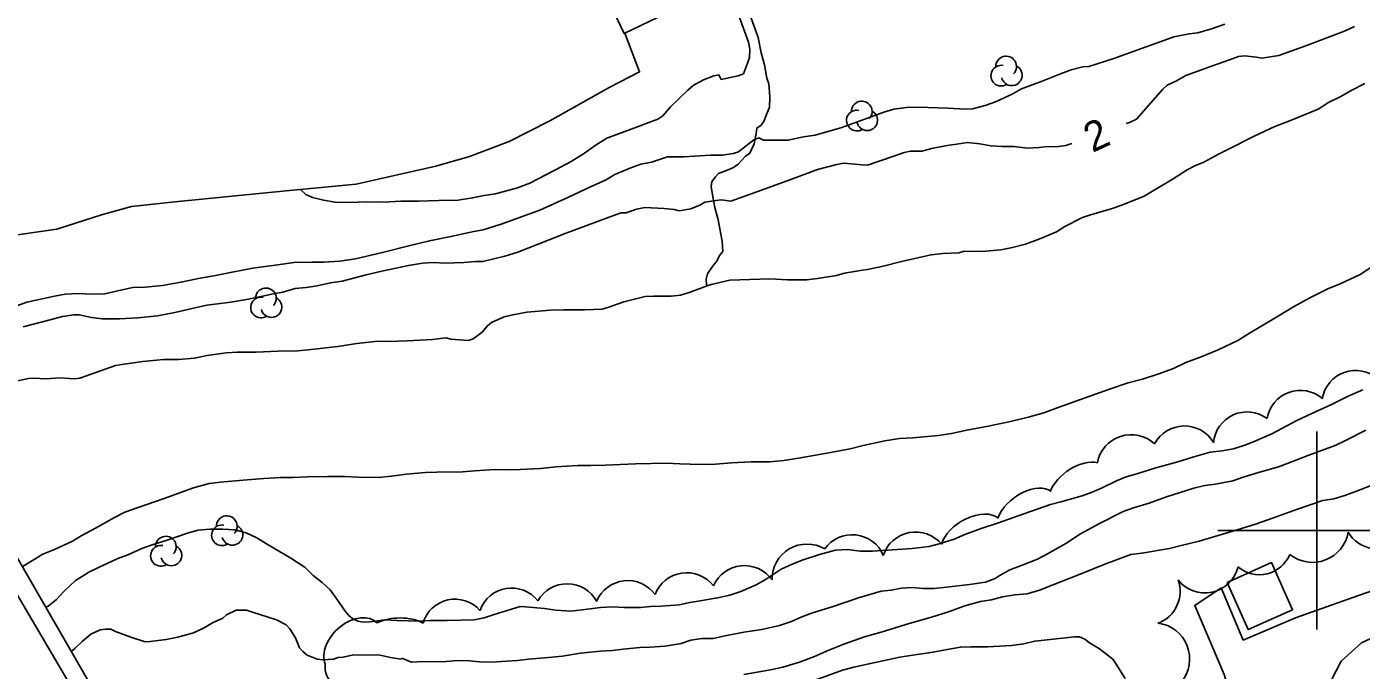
# Model space of a CAD drawing. Extents: x 381879 to 384696, y 5564785 to 5567594.
# Drawn here: x 383869.7 to 384004.5, y 5566385.9 to 5566450.9 of the extents above; entities that cross this region are included whole.
import ezdxf

# ---------------------------------------------------------------- set-up
doc = ezdxf.new("R2010")
doc.units = 0
for name, color, linetype in [('Niveau 19', 7, 'Continuous'), ('Niveau 2', 7, 'Continuous'), ('Niveau 21', 7, 'Continuous'), ('Niveau 26', 7, 'Continuous'), ('Niveau 31', 7, 'Continuous'), ('Niveau 4', 7, 'Continuous'), ('Niveau 44', 7, 'Continuous'), ('Niveau 52', 7, 'Continuous'), ('Niveau 61', 7, 'Continuous')]:
    doc.layers.add(name, color=color, linetype=linetype)

msp = doc.modelspace()

# ---------------------------------------------------------------- linework, layer by layer
at = {"layer": 'Niveau 19'}
msp.add_lwpolyline([(384009.04, 5566371.75), (384005.19, 5566373.71), (384000.87, 5566375.14), (383999.42, 5566377.48), (384000.4, 5566382.81), (384002.46, 5566386.78), (384004.5, 5566388.63), (384007.19, 5566389.9), (384009.07, 5566391.03), (384009.06, 5566392.88), (384007.91, 5566394.71), (384004.22, 5566393.43), (383997.83, 5566391.16), (383992.57, 5566388.92), (383990.33, 5566394.2), (383987.67, 5566392.42), (383990.65, 5566385.45), (383993.25, 5566376.84), (383995.32, 5566369.47), (383995.77, 5566367.6)], dxfattribs=at)
at = {"layer": 'Niveau 2'}
for points in [[(383941.69, 5566451.86), (383942.58, 5566449.36), (383942.72, 5566448.64), (383942.68, 5566447.82), (383942.49, 5566447.22), (383942.08, 5566446.17), (383941.54, 5566445.96), (383939.83, 5566445.59), (383939.6, 5566446.04), (383939.1, 5566445.94), (383938.05, 5566445.56), (383937, 5566444.99), (383936.46, 5566444.49), (383934.73, 5566442.82), (383933.95, 5566441.92), (383933.43, 5566441.58), (383932.8, 5566441.33), (383930.73, 5566440.57), (383928.29, 5566439.64), (383927.2, 5566438.99), (383925.94, 5566438.08), (383924.69, 5566437.31), (383923.03, 5566436.41), (383920.51, 5566435.09), (383919.27, 5566434.64), (383917.04, 5566434.04), (383915.89, 5566433.87), (383914.73, 5566433.62), (383913.08, 5566433.36), (383912.34, 5566433.4)], [(383990.7, 5566451.19), (383989.35, 5566450.69), (383987.98, 5566450.3), (383987.12, 5566450.2), (383985.55, 5566449.91), (383984.91, 5566449.67), (383982.28, 5566448.72), (383979.5, 5566447.7), (383976.97, 5566446.91), (383976.36, 5566446.86), (383975.17, 5566446.55), (383974.1, 5566446.16), (383972.26, 5566445.43), (383970.18, 5566444.65), (383969.21, 5566444.11), (383967.55, 5566443.33)], [(384003.82, 5566450.93), (384002.85, 5566450.51), (384001.27, 5566449.88), (383998.8, 5566448.95), (383996.16, 5566448), (383994.45, 5566447.73), (383993.92, 5566447.84), (383992.7, 5566447.99), (383992.1, 5566447.92), (383991.56, 5566447.72), (383989.45, 5566446.98), (383986.77, 5566445.98)], [(383986.77, 5566445.98), (383985.83, 5566445.45), (383984.89, 5566445), (383984.44, 5566444.6), (383983.72, 5566443.76), (383981.78, 5566441.57), (383981.08, 5566441.25), (383980.75, 5566441.13)], [(383967.55, 5566443.33), (383966.5, 5566442.95), (383965.22, 5566442.61), (383964.48, 5566442.6), (383962.74, 5566442.69), (383959.72, 5566442.8), (383958.54, 5566442.76), (383957.26, 5566442.59), (383956.27, 5566442.27), (383954.6, 5566441.66), (383952.03, 5566440.73), (383949.33, 5566439.96), (383948.15, 5566439.8), (383946.61, 5566439.46), (383944.1, 5566439.46), (383943.64, 5566439.67), (383943.13, 5566439.49), (383942.36, 5566438.87), (383941.57, 5566438.28), (383941.08, 5566438.11), (383939.97, 5566437.95), (383938.76, 5566437.94), (383936.05, 5566437.78), (383934.42, 5566437.75), (383933.92, 5566437.61), (383932.79, 5566437.21), (383931.71, 5566437.01), (383930.71, 5566436.67), (383929.08, 5566435.99), (383928.15, 5566435.4), (383926.7, 5566434.76), (383924.36, 5566433.66), (383921.52, 5566432.37), (383920.3, 5566431.93), (383917.62, 5566430.95), (383915.78, 5566430.37), (383914.84, 5566430.21), (383912.53, 5566429.71), (383910.37, 5566429.29), (383908.28, 5566428.76), (383905.62, 5566428.11), (383902.89, 5566427.44), (383901.33, 5566427.21), (383899.68, 5566427.12), (383898.53, 5566427.13), (383896.67, 5566427.09), (383895.28, 5566426.88), (383892.54, 5566426.5), (383890.43, 5566426.12), (383888.59, 5566425.73), (383887.21, 5566425.5), (383885.27, 5566425.09), (383883.39, 5566424.75), (383881.64, 5566424.58), (383880.42, 5566424.54), (383879.33, 5566424.33), (383877.58, 5566423.93), (383876.26, 5566423.88), (383874.91, 5566423.96), (383873.56, 5566423.87), (383872.48, 5566423.67), (383869.7, 5566423.06), (383868.59, 5566422.68)], [(383975.24, 5566439.11), (383974.64, 5566438.9), (383973.9, 5566438.81), (383972.51, 5566438.79), (383971.94, 5566438.71), (383970.77, 5566438.65), (383969.41, 5566438.81), (383968.2, 5566438.8), (383967.07, 5566438.87), (383965.96, 5566439.07), (383964.71, 5566439.23), (383963.4, 5566439.01), (383962.85, 5566438.94), (383961.25, 5566438.65), (383960.09, 5566438.35), (383958.97, 5566438.33), (383958.33, 5566438.21), (383957.26, 5566437.82), (383954.61, 5566436.91), (383954.06, 5566436.95), (383952.23, 5566437.13), (383951.52, 5566436.98), (383949.58, 5566436.47), (383948.58, 5566436.1), (383946.14, 5566435.22), (383943.45, 5566434.24), (383940.8, 5566433.27), (383939.88, 5566433.41), (383939.28, 5566433.36), (383938.2, 5566433.18), (383937.74, 5566432.92), (383936.76, 5566432.5), (383935.6, 5566432.31), (383935.1, 5566432.43), (383934.06, 5566432.54), (383932.13, 5566432.65), (383931.28, 5566432.47), (383930.23, 5566432.09), (383929.72, 5566432.09), (383929.17, 5566431.89), (383926.45, 5566430.9), (383924.09, 5566430.02), (383922.45, 5566429.36), (383919.3, 5566428.13), (383917.97, 5566427.71), (383915.76, 5566427.18), (383915.03, 5566427.17), (383913.83, 5566427.08), (383911.94, 5566427.02), (383910.77, 5566427.07), (383909.67, 5566427.01), (383908.26, 5566426.77), (383905.57, 5566426.22), (383903.99, 5566425.83), (383901.56, 5566425.18), (383900.36, 5566425.04), (383899.04, 5566424.74), (383897.93, 5566424.57), (383896.8, 5566424.47), (383895.57, 5566424.09), (383894.45, 5566423.89), (383892.08, 5566423.39), (383890.3, 5566423.09), (383887.89, 5566422.76), (383886.4, 5566422.45), (383884.64, 5566422.03), (383882.89, 5566421.69), (383880.92, 5566421.5), (383879.07, 5566421.38), (383877.31, 5566421.4), (383876.23, 5566421.52), (383875.02, 5566421.8), (383874.45, 5566421.79), (383873.32, 5566421.61), (383871.93, 5566421.27), (383869.33, 5566420.58)], [(383912.34, 5566433.4), (383909.27, 5566433.29), (383907.47, 5566433.28), (383905.77, 5566433.19), (383904.11, 5566433.2), (383902.21, 5566433.15), (383900.86, 5566433.19), (383899.66, 5566433.37), (383898.55, 5566433.67), (383897.89, 5566433.96), (383897.35, 5566434.46)], [(383970.42, 5566401.69), (383973.09, 5566402.62), (383974.14, 5566402.89), (383976.29, 5566403.49), (383977.3, 5566403.88), (383978.25, 5566404.28), (383979.75, 5566405.03), (383980.74, 5566405.43), (383981.81, 5566405.73), (383983.75, 5566406.33), (383985.97, 5566406.93), (383987.58, 5566407.45), (383989.22, 5566407.91), (383990.43, 5566408.05), (383991.59, 5566408.26), (383992.82, 5566408.64), (383993.92, 5566409.09), (383995.45, 5566409.77), (383996.45, 5566410.32), (383997.99, 5566411.11), (383999.5, 5566411.83), (384001.47, 5566412.72), (384003.17, 5566413.56), (384004.64, 5566414.2)], [(383907.58, 5566387.08), (383908.55, 5566386.7), (383909.13, 5566386.71), (383912.07, 5566386.75), (383913.24, 5566386.85), (383914.4, 5566386.83), (383915.43, 5566386.71), (383916.62, 5566386.67), (383917.64, 5566386.76), (383919.25, 5566386.84), (383920.37, 5566386.99), (383922.03, 5566387.11), (383923.8, 5566387.3), (383925.64, 5566387.59), (383927.65, 5566387.8), (383928.82, 5566387.85), (383929.95, 5566388.01), (383931.61, 5566388.18), (383932.65, 5566388.2), (383934.19, 5566388.31), (383935.79, 5566388.58), (383936.77, 5566388.9), (383937.89, 5566389.07), (383939.03, 5566389.08), (383940.25, 5566389.35), (383942.11, 5566389.71), (383943.94, 5566389.98), (383945.73, 5566390.38), (383946.93, 5566390.78), (383947.98, 5566391.26), (383949.07, 5566391.67), (383951.13, 5566392.32), (383953.71, 5566393.19), (383955.98, 5566393.85), (383957.01, 5566393.96), (383958.05, 5566394.18), (383959.13, 5566394.22), (383960.24, 5566394.13), (383961.35, 5566394.13), (383962.58, 5566394.25), (383964.92, 5566394.52), (383966.53, 5566394.78), (383967.5, 5566395.13), (383967.91, 5566395.42), (383969, 5566396.02), (383970.08, 5566396.41), (383971.8, 5566397.1), (383972.8, 5566397.63), (383974.65, 5566398.67), (383976.13, 5566399.64), (383978.05, 5566400.7), (383980.45, 5566401.93), (383981.49, 5566402.3), (383983.07, 5566402.77), (383984.81, 5566403.38), (383987.56, 5566404.27), (383988.67, 5566404.53), (383989.76, 5566404.67), (383991.51, 5566405.02), (383992.56, 5566405.4), (383994.11, 5566405.87), (383996.12, 5566406.43), (383997.11, 5566406.79), (383999.19, 5566407.6), (384001.85, 5566408.6), (384002.95, 5566409.11), (384004.95, 5566410.15)], [(383942.11, 5566385.45), (383944.8, 5566385.9), (383946.06, 5566386.19), (383947.73, 5566386.68), (383949.25, 5566387.24), (383950.7, 5566387.89), (383952.24, 5566388.5), (383954.32, 5566389.26), (383955.99, 5566389.73), (383958.83, 5566390.58), (383961.09, 5566391.22), (383962.79, 5566391.78), (383964.44, 5566392.38), (383966.03, 5566392.82), (383967.14, 5566392.98), (383968.25, 5566393.3), (383969.5, 5566393.48), (383970.75, 5566393.59), (383972, 5566393.97), (383973.27, 5566394.47), (383976.11, 5566395.59), (383978.6, 5566396.58), (383981.22, 5566397.55), (383982.31, 5566397.71), (383985.12, 5566398.17), (383986.3, 5566398.48), (383988.12, 5566398.9), (383989.68, 5566399.39), (383991.86, 5566400.01), (383993.92, 5566400.65), (383995.51, 5566401.23), (383998.15, 5566402.19), (384000.62, 5566403.04), (384001.71, 5566403.19), (384002.83, 5566403.52), (384004.01, 5566403.96), (384005.92, 5566404.72)], [(383871.61, 5566392.23), (383871.86, 5566392.36), (383872.69, 5566393.02), (383873.44, 5566393.81), (383874.63, 5566394.95), (383875.5, 5566395.48), (383875.96, 5566395.77), (383876.95, 5566396.25), (383878.9, 5566397.15), (383879.9, 5566397.52), (383881.32, 5566398.16), (383882.37, 5566398.54), (383883.88, 5566399.02), (383885.92, 5566399.74), (383886.99, 5566400.01), (383888.2, 5566400.12), (383889.49, 5566400.13), (383890.7, 5566400.07), (383891.85, 5566399.77), (383892.92, 5566399.25), (383893.9, 5566398.65), (383896.38, 5566397.19), (383897.82, 5566396.26), (383898.63, 5566395.45), (383899.53, 5566394.74), (383900.33, 5566394), (383900.96, 5566393.15), (383901.84, 5566391.84), (383902.21, 5566391.41), (383902.62, 5566391.08), (383903.14, 5566390.82), (383903.72, 5566390.71), (383904.34, 5566390.76), (383905.91, 5566390.96), (383907.06, 5566390.89), (383909.36, 5566390.83), (383910.46, 5566390.89), (383912.15, 5566390.91), (383914.87, 5566390.96), (383915.91, 5566391.15), (383916.92, 5566391.51), (383919.53, 5566392.3), (383920.08, 5566392.27), (383921.98, 5566392.12), (383923.13, 5566391.93), (383924.66, 5566391.85), (383925.79, 5566391.96), (383927.65, 5566392.21), (383928.9, 5566392.28), (383930.02, 5566392.2), (383931.67, 5566392.21), (383932.68, 5566392.31), (383933.78, 5566392.34), (383935.58, 5566392.47), (383936.67, 5566392.73), (383937.7, 5566392.87), (383939.47, 5566393.18), (383940.7, 5566393.47), (383941.81, 5566393.83), (383943.36, 5566394.49), (383944.38, 5566395.09), (383945.91, 5566396.09), (383946.99, 5566396.6), (383948.12, 5566397.02), (383949.75, 5566397.57), (383951.38, 5566398.02), (383952.61, 5566398.08), (383953.88, 5566397.9), (383955.13, 5566397.9), (383956.13, 5566397.98), (383959.13, 5566398.18), (383960.84, 5566398.36), (383961.86, 5566398.64), (383963.38, 5566399.12), (383964.46, 5566399.59), (383966.11, 5566400.21), (383967.83, 5566400.78), (383970.42, 5566401.69)], [(383874.18, 5566387.76), (383874.56, 5566388.06), (383875.34, 5566388.8), (383876.15, 5566389.51), (383877.11, 5566389.94), (383877.66, 5566390.03), (383878.2, 5566390.01), (383878.67, 5566389.8), (383880.19, 5566389.22), (383881.65, 5566388.73), (383882.16, 5566388.76), (383883.78, 5566388.96), (383884.96, 5566389.22), (383886.53, 5566389.64), (383887.54, 5566390.13), (383888.51, 5566390.69), (383889.49, 5566391.13), (383889.87, 5566391.46), (383890.84, 5566391.95), (383891.9, 5566391.94), (383892.41, 5566391.77), (383894.93, 5566390.95), (383895.91, 5566390.47), (383896.27, 5566390.06), (383896.83, 5566389.14), (383897.23, 5566388.13), (383897.57, 5566387.75), (383898.03, 5566387.4), (383899.03, 5566386.97), (383899.61, 5566386.92), (383900.67, 5566386.97), (383901.15, 5566387.14), (383901.65, 5566387.2), (383902.69, 5566387.44), (383903.22, 5566387.4), (383904.29, 5566387.43), (383905.4, 5566387.38), (383906.45, 5566387.15), (383907.49, 5566386.97), (383907.58, 5566387.08)], [(383949.33, 5566384.87), (383952.09, 5566385.88), (383953.24, 5566386.18), (383954.92, 5566386.54), (383957.87, 5566387.18), (383959.62, 5566387.47), (383961.26, 5566387.68), (383962.3, 5566387.9), (383964, 5566388.2), (383965.05, 5566388.22), (383966.75, 5566388.24), (383969.15, 5566388.37), (383970.39, 5566388.54), (383971.51, 5566388.82), (383972.77, 5566388.93), (383975.53, 5566389.23), (383976.03, 5566389.24), (383976.58, 5566389.02), (383977.05, 5566388.64), (383978.05, 5566388.02), (383979.38, 5566386.99), (383979.74, 5566386.48), (383980.65, 5566385.02)]]:
    msp.add_lwpolyline(points, dxfattribs=at)
at = {"layer": 'Niveau 21'}
msp.add_lwpolyline([(383854.29, 5566418.05), (383874.42, 5566383.83), (383880.95, 5566373.16), (383885.5, 5566366.79), (383889.92, 5566359.74), (383896.72, 5566347.61), (383900.04, 5566342.29), (383903.43, 5566339.29), (383907.03, 5566337.3), (383911.81, 5566335.91), (383917.79, 5566335.81), (383922.5, 5566337.53), (383933.1, 5566341.1), (383948.3, 5566346.3), (383960.84, 5566350.67), (383969.28, 5566354.15), (383981.13, 5566359.44), (383987.9, 5566362.39), (383996.34, 5566366.17), (384012.98, 5566373.48)], dxfattribs=at)
at = {"layer": 'Niveau 26'}
msp.add_lwpolyline([(383876.09, 5566384.46), (383851.58, 5566426.94)], dxfattribs=at)
at = {"layer": 'Niveau 31'}
msp.add_lwpolyline([(383934.23, 5566452.25), (383930.04, 5566450.22), (383928.91, 5566452.57)], dxfattribs=at)
msp.add_lwpolyline([(383990.94, 5566394.74), (383995.41, 5566396.75), (383997.55, 5566391.98), (383993.08, 5566389.97)], close=True, dxfattribs=at)
at = {"layer": 'Niveau 4'}
for points in [[(383942.71, 5566452.25), (383943.58, 5566449.82), (383943.88, 5566448.29), (383944.22, 5566447.05), (383944.43, 5566445.72), (383944.64, 5566445.14), (383944.75, 5566443.84), (383944.71, 5566442.78), (383944.34, 5566441.88), (383944.17, 5566441.42), (383943.87, 5566440.95), (383943.42, 5566440.67), (383943.36, 5566440.12), (383943.15, 5566439.07), (383942.72, 5566438.14), (383942.28, 5566437.83), (383941.92, 5566437.42), (383941.56, 5566437.02), (383941.08, 5566436.69), (383940.55, 5566436.46), (383940.09, 5566436.29), (383939.58, 5566436.08), (383939.22, 5566435.72), (383938.88, 5566435.25), (383938.82, 5566434.76), (383938.99, 5566433.72), (383939.18, 5566432.66), (383939.42, 5566431.77), (383939.5, 5566431.56)], [(383973.69, 5566430.2), (383974.55, 5566430.72), (383976.34, 5566431.63), (383977.05, 5566431.86), (383979.22, 5566432.5), (383980.29, 5566432.89), (383982.56, 5566433.8), (383983.22, 5566434.19), (383985.48, 5566435.53), (383986.89, 5566436.46), (383987.68, 5566436.86), (383988.59, 5566437.21), (383990.06, 5566438.03), (383991.02, 5566438.5), (383993.68, 5566439.85), (383995.74, 5566440.84), (383997.33, 5566441.44), (384000.12, 5566442.6), (384001.19, 5566443.25), (384002.43, 5566443.87), (384003.53, 5566444.52), (384004.84, 5566445.19)], [(383939.5, 5566431.56), (383939.92, 5566429.23), (383940, 5566428.19), (383939.66, 5566427.79), (383939.41, 5566427.23), (383939.04, 5566426.78), (383938.46, 5566425.93), (383938.32, 5566425.39), (383938.34, 5566424.86), (383938.41, 5566424.72)], [(383938.41, 5566424.72), (383938.83, 5566424.87), (383940.7, 5566425.3), (383941.71, 5566425.34), (383944.76, 5566425.43), (383946.55, 5566425.32), (383948.5, 5566425.32), (383949.58, 5566425.46), (383951.49, 5566425.77), (383952.28, 5566426), (383954.12, 5566426.31), (383954.63, 5566426.38), (383956.21, 5566426.72), (383958.04, 5566427.2), (383961.03, 5566427.86), (383962.21, 5566428), (383963.83, 5566428.07), (383964.37, 5566428.23), (383964.97, 5566428.19), (383966.57, 5566428.24), (383968.08, 5566428.38), (383969.27, 5566428.61), (383970.57, 5566428.95), (383972.02, 5566429.48), (383973.69, 5566430.2)], [(383893.65, 5566405.26), (383895.34, 5566405.36), (383896.61, 5566405.34), (383898.04, 5566405.41), (383900.06, 5566405.46), (383901.8, 5566405.45), (383903.18, 5566405.39), (383905.21, 5566405.35), (383906.53, 5566405.48), (383908.01, 5566405.69), (383909.97, 5566405.86), (383911.13, 5566405.88), (383913.69, 5566405.92), (383914.93, 5566406.03), (383916.99, 5566406.17), (383918.22, 5566406.12), (383919.54, 5566406.15), (383921.6, 5566406.27), (383923.13, 5566406.44), (383925.36, 5566406.58), (383926.67, 5566406.55), (383928.13, 5566406.59), (383931.18, 5566406.73), (383934.32, 5566406.81), (383935.65, 5566406.72), (383937.75, 5566406.66), (383939.27, 5566406.69), (383940.88, 5566406.83), (383942.87, 5566406.92), (383944.76, 5566406.94), (383946.17, 5566407.06), (383947.64, 5566407.3), (383950.51, 5566407.8), (383952.87, 5566408.26), (383954.18, 5566408.59), (383956.36, 5566409.05), (383957.83, 5566409.29), (383959.18, 5566409.36), (383961.79, 5566409.6), (383963.11, 5566409.81), (383964.64, 5566410.14), (383966.79, 5566410.55), (383969.07, 5566411.02), (383970.96, 5566411.47), (383972.42, 5566411.89), (383973.86, 5566412.41), (383976.61, 5566413.41), (383979.17, 5566414.33), (383980.94, 5566414.92), (383982.39, 5566415.28), (383983.95, 5566415.78), (383985.52, 5566416.38), (383986.78, 5566416.98), (383988.33, 5566417.54), (383990.02, 5566418.26), (383992.02, 5566419.19), (383993.19, 5566419.94), (383995.35, 5566421.23), (383997.65, 5566422.6), (383999.29, 5566423.5), (384001.11, 5566424.42), (384002.34, 5566424.92), (384004.39, 5566425.88), (384005.67, 5566426.72)], [(383868.3, 5566415.03), (383869.87, 5566415.35), (383870.43, 5566415.4), (383871.6, 5566415.34), (383873.1, 5566415.44), (383874.47, 5566415.34), (383875.05, 5566415.38), (383875.63, 5566415.6), (383878.67, 5566416.66), (383879.53, 5566416.82), (383881.43, 5566417.09), (383883.5, 5566417.27), (383885.05, 5566417.28), (383886.65, 5566417.43), (383887.93, 5566417.67), (383889.85, 5566417.94), (383890.95, 5566418.02), (383892.86, 5566418.03), (383895.05, 5566418.11), (383897.08, 5566418.14), (383898.12, 5566418.25), (383901.11, 5566418.59), (383903.05, 5566418.91), (383905.17, 5566419.13), (383906.24, 5566419.1), (383908.11, 5566419.16), (383910.69, 5566419.29), (383912.03, 5566419.46), (383912.54, 5566419.34), (383914.29, 5566419.2), (383914.78, 5566419.37), (383915.69, 5566420.04), (383916.24, 5566420.69), (383916.64, 5566421.01), (383917.93, 5566421.6), (383918.79, 5566421.81), (383920.19, 5566422.06), (383922.6, 5566422.28), (383923.95, 5566422.31), (383926.07, 5566422.29), (383927.82, 5566422.37), (383928.48, 5566422.57), (383930, 5566423.12), (383932.17, 5566423.64), (383933.01, 5566423.67), (383934.78, 5566423.67), (383935.72, 5566423.78), (383936.71, 5566424.1), (383938.41, 5566424.72)], [(383869.24, 5566396.33), (383871.33, 5566397.61), (383872.48, 5566398.07), (383874.3, 5566398.93), (383875.2, 5566399.47), (383876.65, 5566400.24), (383878.55, 5566401.32), (383879.61, 5566401.84), (383880.85, 5566402.29), (383883.48, 5566403.21), (383886.54, 5566404.32), (383888.12, 5566404.75), (383889.27, 5566404.88), (383891.56, 5566405.09), (383893.65, 5566405.26)]]:
    msp.add_lwpolyline(points, dxfattribs=at)
at = {"layer": 'Niveau 44'}
for centre, radius, start, end in [((383998.33, 5566410.76), 3.4, 49.0391, 170.6965), ((383992.95, 5566408.59), 3.39, 53.468, 175.4199), ((383986.63, 5566407.14), 3.42, 30.1482, 151.9629), ((383981.25, 5566406.2), 3.48, 47.2378, 169.3345), ((383959.47, 5566396.41), 3.43, 39.8412, 161.8793), ((383948.5, 5566395.09), 3.53, 59.5404, 181.4001), ((383953.07, 5566396.17), 3.4, 22.6981, 144.7702), ((383936.35, 5566392.32), 3.41, 37.649, 159.3459), ((383942.18, 5566393.05), 3.4, 34.8794, 156.6951), ((383924.27, 5566391.21), 3.4, 28.453, 150.1967), ((383930.4, 5566391.53), 3.4, 35.7574, 157.5833), ((383918.67, 5566390.78), 3.39, 38.6108, 160.4091)]:
    msp.add_arc(centre, radius, start, end, dxfattribs=at)
for centre, major_axis, ratio, start_param, end_param in [((383968.13, 5566445.97), (0.836, -0.629), 0.999875, 2.023129, 5.909704), ((383968.62, 5566446.89), (0.836, -0.629), 0.999875, 6.162675, 10.101684), ((383969.18, 5566446.01), (0.836, -0.629), 0.999875, 4.036058, 8.005933), ((383954.03, 5566442.35), (0.836, -0.629), 0.999875, 6.162675, 10.101684), ((383953.54, 5566441.43), (0.836, -0.629), 0.999875, 2.023129, 5.909704), ((383954.59, 5566441.47), (0.836, -0.629), 0.999875, 4.036058, 8.005933), ((383893.85, 5566423.46), (0.836, -0.629), 0.999875, 6.162675, 10.101684), ((383893.36, 5566422.54), (0.836, -0.629), 0.999875, 2.023129, 5.909704), ((383894.41, 5566422.58), (0.836, -0.629), 0.999875, 4.036058, 8.005933), ((384003.91, 5566412.76), (-1.14, 3.21), 0.999994, 5.217876, 7.345643), ((383975.94, 5566404.36), (-2.77, -1.94), 0.591191, 3.636285, 5.587972), ((383970.65, 5566401.72), (-2.74, -1.97), 0.595064, 3.304074, 5.590123), ((383889.9, 5566400.43), (-0.836, 0.629), 0.999875, 3.020126, 6.959135), ((383965.15, 5566399.26), (-2.93, -1.66), 0.586066, 3.359516, 5.790929), ((383889.41, 5566399.51), (-0.836, 0.629), 0.999875, 5.163765, 9.050341), ((383890.46, 5566399.55), (-0.836, 0.629), 0.999875, 0.893509, 4.863384), ((383999.53, 5566400.48), (1.4, -3.44), 0.99212, 5.235485, 7.295337), ((384006.11, 5566401.52), (3.27, -1.05), 0.985062, 3.977022, 5.787854), ((383883.25, 5566397.44), (-0.836, 0.629), 0.999875, 5.163765, 9.050341), ((383883.74, 5566398.36), (-0.836, 0.629), 0.999875, 3.020126, 6.959135), ((383884.3, 5566397.48), (-0.836, 0.629), 0.999875, 0.893509, 4.863384), ((383994.18, 5566398.94), (0.39, -3.4), 0.986588, 5.479037, 7.327665), ((383988.7, 5566397.05), (3.42, 0.07), 0.985229, 3.771269, 6.040842), ((383982.75, 5566393.83), (1.49, 3.1), 0.999615, 3.94998, 5.509656), ((383912.95, 5566389.68), (0.37, 3.35), 0.99996, 5.549099, 7.674458), ((383902.61, 5566388.33), (-2.45, -2.32), 0.676243, 3.141308, 6.036674), ((383907.28, 5566389.34), (-3.37, -0.1), 0.536357, 3.887968, 5.416561), ((383983.51, 5566387.01), (3.41, 1.28), 0.999921, 5.222571, 7.37216), ((383903.1, 5566385.67), (3.17, -1.14), 0.73069, 3.270493, 5.169382)]:
    msp.add_ellipse(centre, major_axis=major_axis, ratio=ratio, start_param=start_param, end_param=end_param, dxfattribs=at)
at = {"layer": 'Niveau 52'}
msp.add_lwpolyline([(383930.1, 5566450.25), (383931.59, 5566446.35), (383928.59, 5566444.81), (383922.52, 5566441.39), (383918.42, 5566439.32), (383914.4, 5566437.79), (383911, 5566436.83), (383902.95, 5566434.99), (383896.22, 5566434.35), (383884.65, 5566433.22), (383880.27, 5566432.74), (383877.25, 5566431.91), (383872.73, 5566430.46), (383867.11, 5566429.65), (383860.7, 5566428.25), (383858.49, 5566428.36), (383856.51, 5566428.77), (383854.6, 5566428.46), (383853.76, 5566428.15), (383851.4, 5566427.26)], dxfattribs=at)
at = {"layer": 'Niveau 61'}
for points in [[(384000, 5566410), (384000, 5566400), (384000, 5566390)], [(383990, 5566400), (384000, 5566400), (384010, 5566400)]]:
    msp.add_lwpolyline(points, dxfattribs=at)

# ---------------------------------------------------------------- texts
at = {"layer": 'Niveau 2'}
msp.add_text('2', height=3, rotation=24.6973, dxfattribs=at).set_placement((383977.33, 5566438.15))

doc.saveas('drawing.dxf')
